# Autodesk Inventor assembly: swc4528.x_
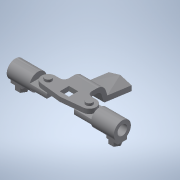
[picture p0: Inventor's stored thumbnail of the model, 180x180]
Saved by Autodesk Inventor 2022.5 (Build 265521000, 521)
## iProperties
Part Number: swc4528.x_
Material: 一般
Document SubType Name: Assembly
Designer: ImaoCorp
Sending System: SOLIDWORKS 2017-2017317
MC: AMD64
MC_MODEL: Intel64 Family 6 Model 60 Stepping 3, GenuineIntel
OS: Windows_NT
FRU: Parasolid Version 29.0, build 201,  4-17-2017
FORMAT: text
GUISE: transmit
KEY: swc4528
FILE: swc4528.x_t
DATE: Wed Sep 18 16:02:41 2019
Author: ImaoCorp
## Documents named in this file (4)
- X:\14_SW2022-Inv2022\00_全2023-1023新製品(TCC)まで\s\swc4528\SWC4528.iam
- X:\14_SW2022-Inv2022\00_全2023-1023新製品(TCC)まで\s\swc4528\swc4528_01.ipt
- X:\14_SW2022-Inv2022\00_全2023-1023新製品(TCC)まで\s\swc4528\swc4528_02.ipt
- X:\14_SW2022-Inv2022\00_全2023-1023新製品(TCC)まで\s\swc4528\swc4528_03.ipt
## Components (3 placed, 3 different names)
1. swc4528_01
2. swc4528_02
3. swc4528_03
